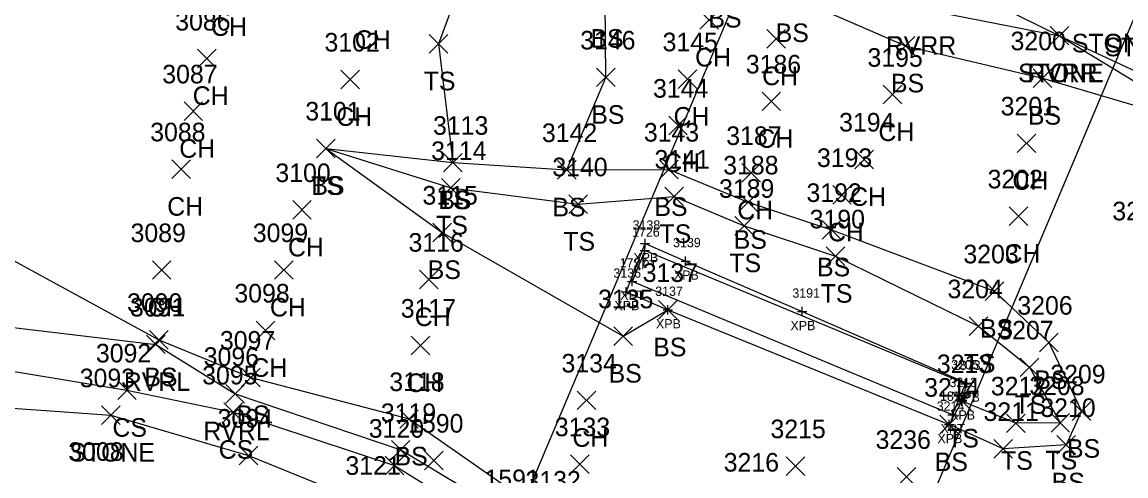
# Model space of a CAD drawing. Extents: x 462930 to 463548, y 29607 to 30453.
# Drawn here: x 463320.55 to 463356.77, y 30125.62 to 30140.5 of the extents above; entities that cross this region are included whole.
import ezdxf

# ---------------------------------------------------------------- set-up
doc = ezdxf.new("R2010")
doc.units = 0
for name, color, linetype in [('B_A', 7, 'Continuous'), ('B_I', 7, 'Continuous'), ('B_TIC', 7, 'Continuous'), ('BSUBM', 7, 'Continuous'), ('L_A', 7, 'Continuous'), ('L_I', 7, 'Continuous'), ('L_TIC', 7, 'Continuous'), ('LASF', 7, 'Continuous'), ('LAWE', 7, 'Continuous'), ('LELB', 7, 'Continuous'), ('UW', 7, 'Continuous')]:
    doc.layers.add(name, color=color, linetype=linetype)

msp = doc.modelspace()

# ---------------------------------------------------------------- linework, layer by layer
at = {"layer": 'B_TIC'}
for p, q in [((463340.994, 30133.236), (463341.017, 30133.236)), ((463340.986, 30133.007), (463341.009, 30133.007)), ((463342.324, 30132.661), (463342.347, 30132.661)), ((463340.569, 30131.996), (463340.592, 30131.996)), ((463340.373, 30131.66), (463340.396, 30131.66)), ((463340.373, 30131.66), (463340.396, 30131.66)), ((463341.736, 30131.064), (463341.759, 30131.064)), ((463346.148, 30131.005), (463346.171, 30131.005)), ((463351.5, 30128.638), (463351.523, 30128.638)), ((463351.544, 30128.66), (463351.567, 30128.66)), ((463351.387, 30128.074), (463351.41, 30128.074)), ((463351.079, 30127.623), (463351.102, 30127.623)), ((463350.97, 30127.3), (463350.993, 30127.3)), ((463350.97, 30127.3), (463350.993, 30127.3))]:
    msp.add_line(p, q, dxfattribs=at)
for points in [[(463340.993, 30133.084), (463340.993, 30133.389)], [(463340.841, 30133.236), (463341.146, 30133.236)], [(463340.985, 30132.855), (463340.985, 30133.159)], [(463340.833, 30133.007), (463341.137, 30133.007)], [(463342.171, 30132.661), (463342.475, 30132.661)], [(463342.323, 30132.508), (463342.323, 30132.813)], [(463340.416, 30131.996), (463340.72, 30131.996)], [(463340.568, 30131.844), (463340.568, 30132.148)], [(463340.219, 30131.66), (463340.524, 30131.66)], [(463340.219, 30131.66), (463340.524, 30131.66)], [(463340.372, 30131.508), (463340.372, 30131.813)], [(463340.372, 30131.508), (463340.372, 30131.813)], [(463341.735, 30130.912), (463341.735, 30131.217)], [(463341.583, 30131.064), (463341.888, 30131.064)], [(463345.994, 30131.005), (463346.299, 30131.005)], [(463346.147, 30130.853), (463346.147, 30131.158)], [(463351.499, 30128.486), (463351.499, 30128.79)], [(463351.543, 30128.508), (463351.543, 30128.812)], [(463351.347, 30128.638), (463351.651, 30128.638)], [(463351.391, 30128.66), (463351.696, 30128.66)], [(463351.233, 30128.074), (463351.538, 30128.074)], [(463351.386, 30127.921), (463351.386, 30128.226)], [(463350.926, 30127.623), (463351.23, 30127.623)], [(463351.078, 30127.471), (463351.078, 30127.775)], [(463350.817, 30127.3), (463351.122, 30127.3)], [(463350.817, 30127.3), (463351.122, 30127.3)], [(463350.969, 30127.148), (463350.969, 30127.453)], [(463350.969, 30127.148), (463350.969, 30127.453)]]:
    msp.add_lwpolyline(points, dxfattribs=at)
at = {"layer": 'BSUBM'}
for points in [[(463340.372, 30131.66), (463340.993, 30133.236), (463342.323, 30132.661), (463346.147, 30131.005), (463351.543, 30128.66), (463351.386, 30128.074), (463350.969, 30127.3)], [(463340.985, 30133.007), (463340.568, 30131.996)], [(463351.499, 30128.638), (463340.985, 30133.007)], [(463351.078, 30127.623), (463340.568, 30131.996)], [(463340.372, 30131.66), (463341.735, 30131.064), (463350.969, 30127.3)], [(463351.078, 30127.623), (463351.499, 30128.638)]]:
    msp.add_lwpolyline(points, dxfattribs=at)
at = {"layer": 'L_TIC'}
for points in [[(463342.789, 30140.264), (463343.398, 30140.874)], [(463343.398, 30140.264), (463342.789, 30140.874)], [(463354.285, 30139.75), (463354.894, 30140.359)], [(463354.894, 30139.75), (463354.285, 30140.359)], [(463354.285, 30139.75), (463354.894, 30140.359)], [(463354.894, 30139.75), (463354.285, 30140.359)], [(463333.909, 30139.483), (463334.518, 30140.092)], [(463334.518, 30139.483), (463333.909, 30140.092)], [(463344.989, 30139.65), (463345.599, 30140.259)], [(463345.599, 30139.65), (463344.989, 30140.259)], [(463349.229, 30139.415), (463349.838, 30140.024)], [(463349.838, 30139.415), (463349.229, 30140.024)], [(463326.308, 30139.003), (463326.918, 30139.613)], [(463326.918, 30139.003), (463326.308, 30139.613)], [(463331.015, 30138.316), (463331.625, 30138.925)], [(463331.625, 30138.316), (463331.015, 30138.925)], [(463339.397, 30138.383), (463340.007, 30138.992)], [(463340.007, 30138.383), (463339.397, 30138.992)], [(463342.082, 30138.324), (463342.692, 30138.933)], [(463342.692, 30138.324), (463342.082, 30138.933)], [(463353.721, 30138.357), (463354.331, 30138.966)], [(463354.331, 30138.357), (463353.721, 30138.966)], [(463344.83, 30137.597), (463345.439, 30138.207)], [(463345.439, 30137.597), (463344.83, 30138.207)], [(463348.804, 30137.817), (463349.414, 30138.427)], [(463349.414, 30137.817), (463348.804, 30138.427)], [(463325.866, 30137.27), (463326.476, 30137.88)], [(463326.476, 30137.27), (463325.866, 30137.88)], [(463341.768, 30136.803), (463342.377, 30137.412)], [(463342.377, 30136.803), (463341.768, 30137.412)], [(463330.214, 30136.054), (463330.824, 30136.663)], [(463330.824, 30136.054), (463330.214, 30136.663)], [(463330.214, 30136.054), (463330.824, 30136.663)], [(463330.824, 30136.054), (463330.214, 30136.663)], [(463330.214, 30136.054), (463330.824, 30136.663)], [(463330.824, 30136.054), (463330.214, 30136.663)], [(463353.196, 30136.22), (463353.806, 30136.83)], [(463353.806, 30136.22), (463353.196, 30136.83)], [(463347.874, 30135.692), (463348.484, 30136.302)], [(463348.484, 30135.692), (463347.874, 30136.302)], [(463325.471, 30135.371), (463326.081, 30135.98)], [(463326.081, 30135.371), (463325.471, 30135.98)], [(463334.379, 30135.586), (463334.989, 30136.196)], [(463334.989, 30135.586), (463334.379, 30136.196)], [(463334.379, 30135.586), (463334.989, 30136.196)], [(463334.989, 30135.586), (463334.379, 30136.196)], [(463338.123, 30135.348), (463338.733, 30135.957)], [(463338.733, 30135.348), (463338.123, 30135.957)], [(463338.123, 30135.348), (463338.733, 30135.957)], [(463338.733, 30135.348), (463338.123, 30135.957)], [(463341.469, 30135.362), (463342.079, 30135.972)], [(463342.079, 30135.362), (463341.469, 30135.972)], [(463344.171, 30135.251), (463344.781, 30135.86)], [(463344.781, 30135.251), (463344.171, 30135.86)], [(463334.317, 30134.757), (463334.927, 30135.367)], [(463334.927, 30134.757), (463334.317, 30135.367)], [(463338.491, 30134.225), (463339.101, 30134.834)], [(463339.101, 30134.225), (463338.491, 30134.834)], [(463341.645, 30134.476), (463342.254, 30135.086)], [(463342.254, 30134.476), (463341.645, 30135.086)], [(463344.071, 30134.286), (463344.681, 30134.895)], [(463344.681, 30134.286), (463344.071, 30134.895)], [(463347.147, 30134.529), (463347.756, 30135.139)], [(463347.756, 30134.529), (463347.147, 30135.139)], [(463329.432, 30134.035), (463330.041, 30134.645)], [(463330.041, 30134.035), (463329.432, 30134.645)], [(463343.937, 30133.518), (463344.546, 30134.127)], [(463344.546, 30133.518), (463343.937, 30134.127)], [(463352.941, 30133.828), (463353.55, 30134.438)], [(463353.55, 30133.828), (463352.941, 30134.438)], [(463334.032, 30133.296), (463334.642, 30133.905)], [(463334.642, 30133.296), (463334.032, 30133.905)], [(463346.802, 30133.383), (463347.412, 30133.992)], [(463347.412, 30133.383), (463346.802, 30133.992)], [(463346.934, 30132.517), (463347.544, 30133.127)], [(463347.544, 30132.517), (463346.934, 30133.127)], [(463324.828, 30132.066), (463325.438, 30132.676)], [(463325.438, 30132.066), (463324.828, 30132.676)], [(463328.839, 30132.066), (463329.449, 30132.675)], [(463329.449, 30132.066), (463328.839, 30132.675)], [(463333.591, 30131.752), (463334.2, 30132.361)], [(463334.2, 30131.752), (463333.591, 30132.361)], [(463352.148, 30131.37), (463352.758, 30131.98)], [(463352.758, 30131.37), (463352.148, 30131.98)], [(463341.431, 30130.76), (463342.04, 30131.369)], [(463342.04, 30130.76), (463341.431, 30131.369)], [(463328.231, 30130.085), (463328.841, 30130.695)], [(463328.841, 30130.085), (463328.231, 30130.695)], [(463339.967, 30129.897), (463340.576, 30130.506)], [(463340.576, 30129.897), (463339.967, 30130.506)], [(463351.626, 30130.225), (463352.235, 30130.835)], [(463352.235, 30130.225), (463351.626, 30130.835)], [(463324.633, 30129.627), (463325.243, 30130.236)], [(463325.243, 30129.627), (463324.633, 30130.236)], [(463324.737, 30129.777), (463325.346, 30130.386)], [(463325.346, 30129.777), (463324.737, 30130.386)], [(463333.321, 30129.589), (463333.93, 30130.198)], [(463333.93, 30129.589), (463333.321, 30130.198)], [(463353.934, 30129.687), (463354.544, 30130.296)], [(463354.544, 30129.687), (463353.934, 30130.296)], [(463353.295, 30128.875), (463353.904, 30129.484)], [(463353.904, 30128.875), (463353.295, 30129.484)], [(463327.757, 30128.54), (463328.367, 30129.149)], [(463328.367, 30128.54), (463327.757, 30129.149)], [(463323.69, 30128.121), (463324.3, 30128.731)], [(463324.3, 30128.121), (463323.69, 30128.731)], [(463327.243, 30128.008), (463327.852, 30128.618)], [(463327.852, 30128.008), (463327.243, 30128.618)], [(463338.766, 30127.791), (463339.376, 30128.401)], [(463339.376, 30127.791), (463338.766, 30128.401)], [(463351.081, 30127.769), (463351.69, 30128.378)], [(463351.69, 30127.769), (463351.081, 30128.378)], [(463327.176, 30127.4), (463327.785, 30128.01)], [(463327.785, 30127.4), (463327.176, 30128.01)], [(463355.003, 30127.434), (463355.612, 30128.043)], [(463355.612, 30127.434), (463355.003, 30128.043)], [(463323.159, 30127.307), (463323.768, 30127.916)], [(463323.768, 30127.307), (463323.159, 30127.916)], [(463332.944, 30127.181), (463333.553, 30127.79)], [(463333.553, 30127.181), (463332.944, 30127.79)], [(463350.664, 30126.995), (463351.274, 30127.605)], [(463351.274, 30126.995), (463350.664, 30127.605)], [(463352.85, 30127.039), (463353.46, 30127.648)], [(463353.46, 30127.039), (463352.85, 30127.648)], [(463354.309, 30127.05), (463354.918, 30127.66)], [(463354.918, 30127.05), (463354.309, 30127.66)], [(463354.502, 30126.331), (463355.111, 30126.941)], [(463355.111, 30126.331), (463354.502, 30126.941)], [(463327.68, 30125.981), (463328.29, 30126.591)], [(463328.29, 30125.981), (463327.68, 30126.591)], [(463332.67, 30126.165), (463333.28, 30126.775)], [(463333.28, 30126.165), (463332.67, 30126.775)], [(463352.438, 30126.201), (463353.048, 30126.81)], [(463353.048, 30126.201), (463352.438, 30126.81)], [(463332.47, 30125.652), (463333.08, 30126.261)], [(463333.08, 30125.652), (463332.47, 30126.261)], [(463333.761, 30125.819), (463334.371, 30126.429)], [(463334.371, 30125.819), (463333.761, 30126.429)], [(463338.548, 30125.7), (463339.158, 30126.309)], [(463339.158, 30125.7), (463338.548, 30126.309)], [(463345.621, 30125.636), (463346.23, 30126.245)], [(463346.23, 30125.636), (463345.621, 30126.245)], [(463349.259, 30125.286), (463349.869, 30125.895)], [(463349.869, 30125.286), (463349.259, 30125.895)]]:
    msp.add_lwpolyline(points, dxfattribs=at)
at = {"layer": 'LASF'}
for points in [[(463335.666, 30151.825), (463334.307, 30149.365), (463333.551, 30148), (463337.382, 30145.968), (463341.269, 30144.863), (463346.266, 30143.58), (463350.176, 30142.23), (463354.589, 30140.054), (463359.587, 30137.022), (463360.802, 30137.163)], [(463302.508, 30136.744), (463309.807, 30134.07), (463314.097, 30132.787), (463314.835, 30129.355), (463318.543, 30127.958), (463323.464, 30127.612), (463327.985, 30126.286), (463331.81, 30124.74), (463337.174, 30122.457), (463335.599, 30120.018), (463340.457, 30118.077), (463343.625, 30116.989)]]:
    msp.add_lwpolyline(points, dxfattribs=at)
at = {"layer": 'LAWE'}
for points in [[(463312.771, 30156.48), (463317.927, 30154.119), (463323.301, 30150.297), (463329.2, 30147.672), (463333.781, 30145.982), (463336.917, 30145.16), (463341.124, 30143.089), (463345.902, 30142.661), (463349.953, 30140.952), (463354.589, 30140.054), (463360.802, 30137.163), (463361.685, 30137.202), (463364.938, 30136.029), (463367.213, 30134.485), (463367.529, 30133.847), (463370.878, 30131.969), (463372.536, 30131.581), (463374.072, 30131.794), (463376.13, 30130.821), (463379.432, 30129.045)], [(463303.761, 30138.951), (463311.513, 30136.497), (463315.004, 30134.116), (463316.958, 30131.951), (463319.339, 30130.596), (463324.938, 30129.932), (463327.547, 30128.313), (463332.975, 30126.47), (463337.641, 30123.674), (463341.966, 30121.958), (463344.49, 30119.626), (463346.795, 30118.444), (463349.584, 30118.528), (463352.681, 30116.677), (463355.961, 30113.875), (463359.993, 30113.221), (463365.135, 30110.482), (463368.778, 30108.638), (463372.593, 30105.432)]]:
    msp.add_lwpolyline(points, dxfattribs=at)
at = {"layer": 'LELB'}
for points in [[(463311.51, 30154.564), (463317.305, 30152.12), (463328.108, 30145.648), (463332.48, 30143.532), (463335.24, 30142.565), (463339.678, 30141.183), (463343.544, 30141.846), (463345.752, 30141.37), (463349.534, 30139.719), (463354.026, 30138.661), (463359.587, 30137.022), (463361.306, 30136.712), (463364.334, 30135.56), (463366.649, 30133.733), (463367.281, 30133.213), (463370.369, 30131.577), (463372.89, 30130.394), (463376, 30129.47), (463379.084, 30127.97)], [(463335.24, 30142.565), (463334.214, 30139.787), (463334.684, 30135.891)], [(463338.428, 30135.653), (463339.702, 30138.688), (463339.678, 30141.183)], [(463303.951, 30140.018), (463311.358, 30137.763), (463317.49, 30134.193), (463325.042, 30130.081), (463328.062, 30128.844), (463333.248, 30127.486), (463337.89, 30124.253), (463342.916, 30122.365), (463345.021, 30120.043), (463346.984, 30119.167), (463349.819, 30119.192), (463353.514, 30117.826), (463357.518, 30115.65), (463360.726, 30114.785), (463365.845, 30111.76), (463369.152, 30109.504), (463372.544, 30107.449)], [(463303.076, 30138.323), (463311.018, 30135.245), (463314.543, 30133.39), (463316.477, 30129.737), (463318.725, 30129.305), (463323.995, 30128.426), (463327.48, 30127.705), (463332.775, 30125.956), (463337.384, 30123.1), (463341.878, 30121.285), (463344.206, 30119.085), (463346.364, 30117.777), (463348.209, 30116.851), (463350.137, 30117.27)], [(463330.519, 30136.358), (463334.684, 30135.891), (463338.428, 30135.653), (463341.774, 30135.667), (463344.376, 30134.59), (463347.107, 30133.687), (463352.453, 30131.675), (463354.239, 30129.991), (463355.307, 30127.738), (463354.807, 30126.636), (463352.743, 30126.506), (463350.969, 30127.3)], [(463330.519, 30136.358), (463334.337, 30133.6), (463340.271, 30130.202), (463341.735, 30131.064)], [(463330.519, 30136.358), (463334.622, 30135.062), (463338.796, 30134.53), (463341.949, 30134.781), (463344.241, 30133.823), (463347.239, 30132.822), (463351.93, 30130.53), (463353.599, 30129.179), (463354.613, 30127.355), (463353.155, 30127.343), (463351.386, 30128.074)]]:
    msp.add_lwpolyline(points, dxfattribs=at)
at = {"layer": 'UW'}
for points in [[(463346.016, 30146.118), (463335.205, 30120.517)], [(463344.573, 30111.096), (463359.121, 30145.596)]]:
    msp.add_lwpolyline(points, dxfattribs=at)

# ---------------------------------------------------------------- texts
at = {"layer": 'B_A'}
for s, p in [('XPT', (463340.595, 30132.397)), ('XPB', (463340.608, 30132.627)), ('XPB', (463341.938, 30132.051)), ('XPT', (463340.178, 30131.386)), ('XPB', (463339.986, 30131.051)), ('XPB', (463339.986, 30131.051)), ('XPB', (463341.35, 30130.455)), ('XPB', (463345.762, 30130.396)), ('XPT', (463351.109, 30128.028)), ('XPB', (463351.158, 30128.05)), ('XPB', (463351, 30127.464)), ('XPT', (463350.688, 30127.013)), ('XPB', (463350.584, 30126.691)), ('XPB', (463350.584, 30126.691))]:
    msp.add_text(s, height=0.3048, dxfattribs=at).set_placement(p)
at = {"layer": 'B_I'}
for s, p in [('1726', (463340.566, 30133.464)), ('3138', (463340.583, 30133.694)), ('3139', (463341.911, 30133.118)), ('1727', (463340.158, 30132.453)), ('3136', (463339.953, 30132.118)), ('3136', (463339.953, 30132.118)), ('3137', (463341.325, 30131.522)), ('3191', (463345.823, 30131.462)), ('3205', (463351.034, 30129.117)), ('1873', (463351.089, 30129.095)), ('3213', (463350.975, 30128.531)), ('1872', (463350.668, 30128.08)), ('3214', (463350.559, 30127.757)), ('3214', (463350.559, 30127.757))]:
    msp.add_text(s, height=0.3048, dxfattribs=at).set_placement(p)
at = {"layer": 'L_A'}
for s, p in [('CH', (463326.752, 30140.047)), ('BS', (463343.069, 30140.322)), ('BS', (463339.203, 30139.659)), ('BS', (463339.203, 30139.659)), ('BS', (463345.276, 30139.846)), ('CH', (463331.469, 30139.621)), ('RVRR', (463348.89, 30139.428)), ('STONE', (463354.992, 30139.507)), ('STONE', (463356.068, 30139.379)), ('CH', (463342.633, 30139.045)), ('TS', (463333.729, 30138.263)), ('CH', (463344.833, 30138.43)), ('BS', (463349.058, 30138.195)), ('STONE', (463353.231, 30138.53)), ('RVRR', (463353.526, 30138.53)), ('CH', (463326.152, 30137.784)), ('BS', (463339.227, 30137.164)), ('BS', (463353.551, 30137.137)), ('CH', (463330.859, 30137.097)), ('CH', (463341.926, 30137.105)), ('CH', (463348.648, 30136.598)), ('CH', (463325.71, 30136.051)), ('CH', (463344.674, 30136.378)), ('CH', (463341.612, 30135.583)), ('CH', (463353.04, 30135.001)), ('TS', (463330.034, 30134.834)), ('BS', (463330.044, 30134.834)), ('BS', (463330.044, 30134.834)), ('TS', (463334.199, 30134.367)), ('BS', (463334.209, 30134.367)), ('CH', (463347.718, 30134.473)), ('CH', (463325.315, 30134.152)), ('BS', (463337.953, 30134.129)), ('BS', (463337.953, 30134.129)), ('BS', (463341.299, 30134.143)), ('CH', (463344.015, 30134.031)), ('TS', (463334.137, 30133.538)), ('TS', (463341.465, 30133.257)), ('CH', (463346.991, 30133.31)), ('CH', (463329.276, 30132.816)), ('TS', (463338.311, 30133.006)), ('BS', (463343.901, 30133.066)), ('CH', (463352.785, 30132.609)), ('BS', (463333.862, 30132.076)), ('TS', (463343.757, 30132.299)), ('BS', (463346.632, 30132.163)), ('TS', (463346.754, 30131.298)), ('CH', (463324.672, 30130.847)), ('CH', (463328.683, 30130.847)), ('CH', (463333.435, 30130.532)), ('BS', (463351.978, 30130.151)), ('BS', (463341.26, 30129.54)), ('CH', (463328.075, 30128.866)), ('TS', (463351.446, 30129.006)), ('BS', (463324.566, 30128.557)), ('BS', (463339.796, 30128.678)), ('BS', (463353.764, 30128.467)), ('RVRL', (463323.891, 30128.408)), ('CH', (463333.165, 30128.37)), ('TS', (463353.115, 30127.655)), ('BS', (463327.587, 30127.32)), ('CS', (463323.52, 30126.902)), ('RVRL', (463326.501, 30126.789)), ('CH', (463338.61, 30126.572)), ('TS', (463350.901, 30126.55)), ('STONE', (463322.105, 30126.088)), ('CS', (463327.005, 30126.181)), ('BS', (463332.773, 30125.962)), ('BS', (463354.832, 30126.214)), ('BS', (463350.494, 30125.776)), ('TS', (463352.67, 30125.819)), ('TS', (463354.129, 30125.831)), ('BS', (463354.331, 30125.112))]:
    msp.add_text(s, height=0.6096, dxfattribs=at).set_placement(p)
at = {"layer": 'L_I'}
for s, p in [('3086', (463325.579, 30140.223)), ('3102', (463330.475, 30139.535)), ('3146', (463338.864, 30139.602)), ('3145', (463341.566, 30139.543)), ('3200', (463352.982, 30139.576)), ('3195', (463348.288, 30139.036)), ('3186', (463344.297, 30138.816)), ('3087', (463325.153, 30138.49)), ('3144', (463341.252, 30138.022)), ('3101', (463329.847, 30137.273)), ('3101', (463329.847, 30137.273)), ('3101', (463329.847, 30137.273)), ('3201', (463352.656, 30137.439)), ('3113', (463334.036, 30136.805)), ('3113', (463334.036, 30136.805)), ('3194', (463347.358, 30136.912)), ('3088', (463324.758, 30136.59)), ('3142', (463337.608, 30136.567)), ('3142', (463337.608, 30136.567)), ('3143', (463340.953, 30136.581)), ('3187', (463343.655, 30136.47)), ('3114', (463333.974, 30135.977)), ('3141', (463341.301, 30135.695)), ('3193', (463346.631, 30135.749)), ('3140', (463337.949, 30135.444)), ('3188', (463343.555, 30135.505)), ('3100', (463328.865, 30135.254)), ('3202', (463352.228, 30135.047)), ('3189', (463343.418, 30134.737)), ('3192', (463346.287, 30134.602)), ('3115', (463333.689, 30134.515)), ('3262', (463356.321, 30133.999)), ('3190', (463346.392, 30133.736)), ('3089', (463324.113, 30133.285)), ('3099', (463328.124, 30133.285)), ('3116', (463333.231, 30132.971)), ('3203', (463351.435, 30132.589)), ('3137', (463340.915, 30131.979)), ('3204', (463350.913, 30131.445)), ('3090', (463323.998, 30130.996)), ('3098', (463327.519, 30131.304)), ('3135', (463339.451, 30131.116)), ('3091', (463324.093, 30130.846)), ('3117', (463332.978, 30130.808)), ('3206', (463353.205, 30130.906)), ('3207', (463352.582, 30130.094)), ('3097', (463327.044, 30129.759)), ('3092', (463322.977, 30129.34)), ('3096', (463326.513, 30129.227)), ('3134', (463338.25, 30129.01)), ('3213', (463350.565, 30128.988)), ('3093', (463322.446, 30128.526)), ('3095', (463326.463, 30128.619)), ('3209', (463354.287, 30128.653)), ('3118', (463332.601, 30128.4)), ('3214', (463350.148, 30128.215)), ('3212', (463352.334, 30128.258)), ('3208', (463353.596, 30128.269)), ('3119', (463332.324, 30127.385)), ('3211', (463352.095, 30127.42)), ('3210', (463353.959, 30127.551)), ('3094', (463326.968, 30127.201)), ('1590', (463333.219, 30127.038)), ('3120', (463331.928, 30126.871)), ('3133', (463338.032, 30126.919)), ('3215', (463345.105, 30126.855)), ('3236', (463348.554, 30126.505)), ('3008', (463322.07, 30126.111)), ('3121', (463331.162, 30125.654)), ('3216', (463343.572, 30125.76)), ('1591', (463335.725, 30125.217)), ('3132', (463337.069, 30125.168))]:
    msp.add_text(s, height=0.6096, dxfattribs=at).set_placement(p)

doc.saveas('drawing.dxf')
